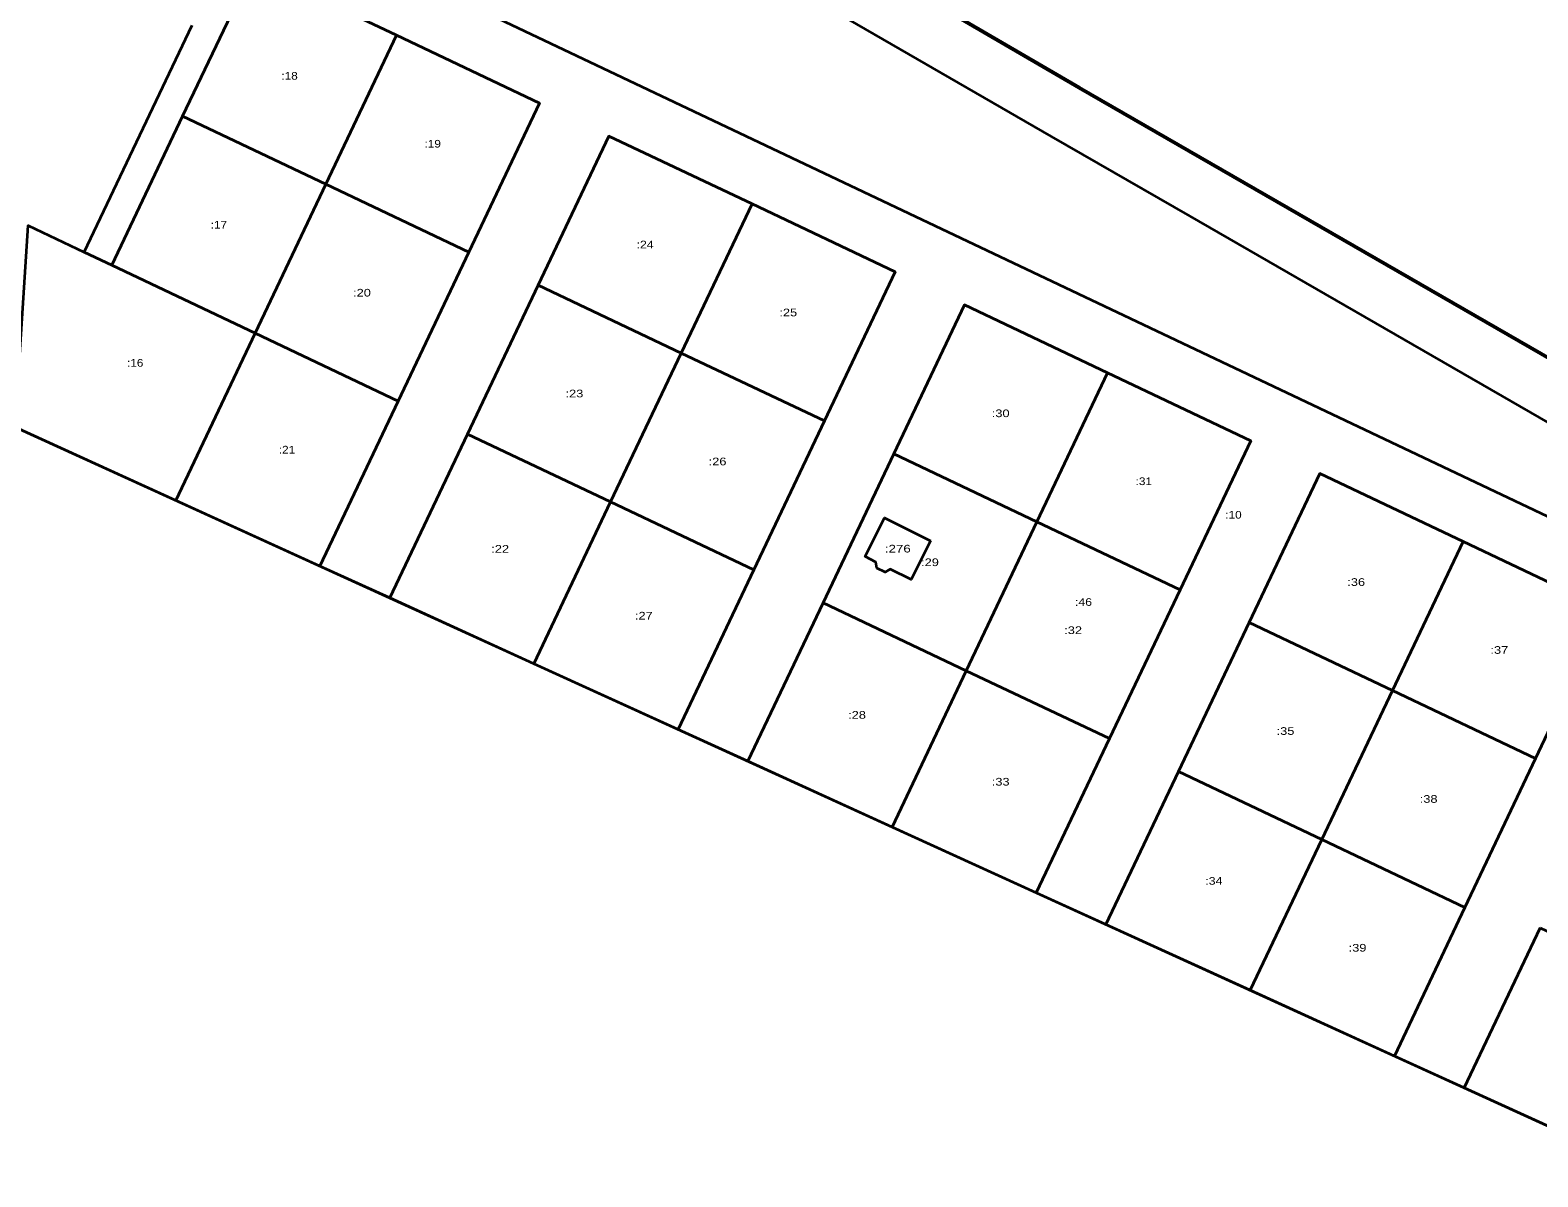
# Model space of a CAD drawing. Extents: x 1178597 to 1179642, y 361068 to 362800.
# Drawn here: x 1178894.1 to 1179189.1, y 362426.5 to 362650.8 of the extents above; entities that cross this region are included whole.
import ezdxf
from ezdxf.enums import TextEntityAlignment as Align

# ---------------------------------------------------------------- set-up
doc = ezdxf.new("R2010")
doc.units = 0
doc.header["$LTSCALE"] = 0.6
for name, color, linetype, lineweight in [('2', 7, 'Continuous', 35), ('4', 7, 'Continuous', 53), ('8', 7, 'Continuous', 35)]:
    doc.layers.add(name, color=color, linetype=linetype, lineweight=lineweight)

msp = doc.modelspace()

# ---------------------------------------------------------------- linework, layer by layer
at = {"layer": '2'}
for points in [[(1179246.62, 362542.08), (1179121.07, 362614.45), (1179093.9, 362630.05), (1178981.79, 362694.75), (1178925.71, 362727.03), (1178817.77, 362789.43), (1178815.61, 362790.67), (1178821.45, 362800.01), (1178902.42, 362753.3), (1178931.11, 362736.59), (1178987.29, 362704.27), (1179073.43, 362654.63), (1179099.35, 362639.55), (1179126.54, 362623.96), (1179252.11, 362551.57)], [(1178937.29, 362676.13), (1179271.17, 362517.67)], [(1179189.51, 362475.25), (1179174.63, 362443.93), (1179160.99, 362450.15), (1179174.79, 362479.23), (1179188.61, 362508.37), (1179202.44, 362537.51), (1179174.44, 362550.8), (1179146.44, 362564.09), (1179132.6, 362534.95), (1179118.77, 362505.81), (1179104.57, 362475.88), (1179090.92, 362482.1), (1179105.23, 362512.24), (1179119.06, 362541.38), (1179132.88, 362570.52), (1179104.88, 362583.81), (1179076.87, 362597.1), (1179063.05, 362567.96), (1179049.22, 362538.82), (1179034.51, 362507.83), (1179020.86, 362514.05), (1179035.66, 362545.25), (1179049.5, 362574.39), (1179063.33, 362603.53), (1179035.32, 362616.83), (1179007.32, 362630.12), (1178993.49, 362600.97), (1178979.66, 362571.83), (1178964.45, 362539.76), (1178950.79, 362545.99), (1178966.11, 362578.26), (1178979.93, 362607.4), (1178993.77, 362636.54), (1178965.76, 362649.83), (1178937.76, 362663.12), (1178923.93, 362633.98), (1178910.1, 362604.84), (1178904.68, 362607.42), (1178925.76, 362651.84)]]:
    msp.add_lwpolyline(points, dxfattribs=at)
for points in [[(1178937.76, 362663.12), (1178965.76, 362649.83), (1178951.93, 362620.69), (1178923.93, 362633.98)], [(1178965.76, 362649.83), (1178993.77, 362636.54), (1178979.93, 362607.4), (1178951.93, 362620.69)], [(1178923.93, 362633.98), (1178951.93, 362620.69), (1178938.1, 362591.55), (1178910.1, 362604.84)], [(1179007.32, 362630.12), (1179035.32, 362616.83), (1179021.49, 362587.68), (1178993.49, 362600.97)], [(1178951.93, 362620.69), (1178979.93, 362607.4), (1178966.11, 362578.26), (1178938.1, 362591.55)], [(1179035.32, 362616.83), (1179063.33, 362603.53), (1179049.5, 362574.39), (1179021.49, 362587.68)], [(1178910.1, 362604.84), (1178938.1, 362591.55), (1178922.58, 362558.86), (1178891.19, 362573.17), (1178893.68, 362612.64), (1178904.68, 362607.42)], [(1178993.49, 362600.97), (1179021.49, 362587.68), (1179007.66, 362558.54), (1178979.66, 362571.83)], [(1179076.87, 362597.1), (1179104.88, 362583.81), (1179091.06, 362554.67), (1179063.05, 362567.96)], [(1178938.1, 362591.55), (1178966.11, 362578.26), (1178950.79, 362545.99), (1178922.58, 362558.86)], [(1179021.49, 362587.68), (1179049.5, 362574.39), (1179035.66, 362545.25), (1179007.66, 362558.54)], [(1179104.88, 362583.81), (1179132.88, 362570.52), (1179119.06, 362541.38), (1179091.06, 362554.67)], [(1178891.19, 362573.17), (1179267.04, 362401.8), (1179192.55, 362243.52), (1179468.78, 362106.45), (1179321.34, 361904.3), (1179281.73, 361911.69), (1179245.3, 361911.43), (1179204.36, 361904.31), (1179180.02, 361887.37), (1179148.05, 361900.8), (1179128.65, 361905.22), (1179097.75, 361928.91), (1179058.81, 361961.65), (1179007.74, 362014.5), (1178950.38, 362075.56), (1178913.62, 362120.85), (1178888.23, 362168.49), (1178869.92, 362263.16), (1178889.76, 362516.06)], [(1178979.66, 362571.83), (1179007.66, 362558.54), (1178992.65, 362526.91), (1178964.45, 362539.76)], [(1179063.05, 362567.96), (1179091.06, 362554.67), (1179077.22, 362525.53), (1179049.22, 362538.82)], [(1179146.44, 362564.09), (1179174.44, 362550.8), (1179160.61, 362521.66), (1179132.6, 362534.95)], [(1179007.66, 362558.54), (1179035.66, 362545.25), (1179020.86, 362514.05), (1178992.65, 362526.91)], [(1179091.06, 362554.67), (1179119.06, 362541.38), (1179105.23, 362512.24), (1179077.22, 362525.53)], [(1179174.44, 362550.8), (1179202.44, 362537.51), (1179188.61, 362508.37), (1179160.61, 362521.66)], [(1179049.22, 362538.82), (1179077.22, 362525.53), (1179062.71, 362494.96), (1179034.51, 362507.83)], [(1179132.6, 362534.95), (1179160.61, 362521.66), (1179146.78, 362492.52), (1179118.77, 362505.81)], [(1179077.22, 362525.53), (1179105.23, 362512.24), (1179090.92, 362482.1), (1179062.71, 362494.96)], [(1179160.61, 362521.66), (1179188.61, 362508.37), (1179174.79, 362479.23), (1179146.78, 362492.52)], [(1179118.77, 362505.81), (1179146.78, 362492.52), (1179132.78, 362463.02), (1179104.57, 362475.88)], [(1179146.78, 362492.52), (1179174.79, 362479.23), (1179160.99, 362450.15), (1179132.78, 362463.02)], [(1179189.51, 362475.25), (1179217.19, 362462.12), (1179199.57, 362432.57), (1179174.63, 362443.93)]]:
    msp.add_lwpolyline(points, close=True, dxfattribs=at)
at = {"layer": '4'}
msp.add_lwpolyline([(1179252.11, 362551.57), (1179099.35, 362639.55), (1179073.43, 362654.63), (1178987.29, 362704.27), (1178931.11, 362736.59), (1178902.42, 362753.3), (1178821.45, 362800.01)], dxfattribs=at)
at = {"layer": '8'}
msp.add_lwpolyline([(1179070.25, 362550.96), (1179066.46, 362543.36), (1179062.38, 362545.39), (1179061.34, 362544.81), (1179059.71, 362545.61), (1179059.56, 362546.79), (1179057.43, 362547.86), (1179061.21, 362555.45)], close=True, dxfattribs=at)

# ---------------------------------------------------------------- texts
at = {"layer": '2'}
for s, width, p in [(':18', 1.15, (1178944.845, 362641.155)), (':19', 1.15, (1178972.85, 362627.865)), (':17', 1.15, (1178931.015, 362612.015)), (':24', 1.2, (1179014.404, 362608.15)), (':20', 1.25, (1178959.015, 362598.725)), (':25', 1.25, (1179042.41, 362594.86)), (':16', 1.15, (1178914.645, 362585)), (':23', 1.25, (1179000.575, 362579.005)), (':30', 1.25, (1179083.965, 362575.135)), (':21', 1.15, (1178944.345, 362568.02)), (':26', 1.25, (1179028.579, 362565.715)), (':31', 1.15, (1179111.97, 362561.845)), (':10', 1.15, (1179129.515, 362555.285)), (':22', 1.25, (1178986.055, 362548.62)), (':29', 1.25, (1179070.14, 362545.995)), (':36', 1.25, (1179153.519, 362542.125)), (':46', 1.2, (1179100.17, 362538.215)), (':27', 1.25, (1179014.154, 362535.545)), (':32', 1.25, (1179098.14, 362532.705)), (':37', 1.25, (1179181.525, 362528.835)), (':28', 1.25, (1179055.864, 362516.14)), (':35', 1.25, (1179139.69, 362512.985)), (':33', 1.25, (1179083.969, 362503.065)), (':38', 1.25, (1179167.694, 362499.695)), (':34', 1.2, (1179125.674, 362483.665)), (':39', 1.25, (1179153.785, 362470.585))]:
    msp.add_text(s, height=1.5, dxfattribs=dict(at, width=width)).set_placement(p, align=Align.CENTER)
at = {"layer": '8', "width": 1.3}
msp.add_text(':276', height=1.5, dxfattribs=at).set_placement((1179063.84, 362548.655), align=Align.CENTER)

doc.saveas('drawing.dxf')
